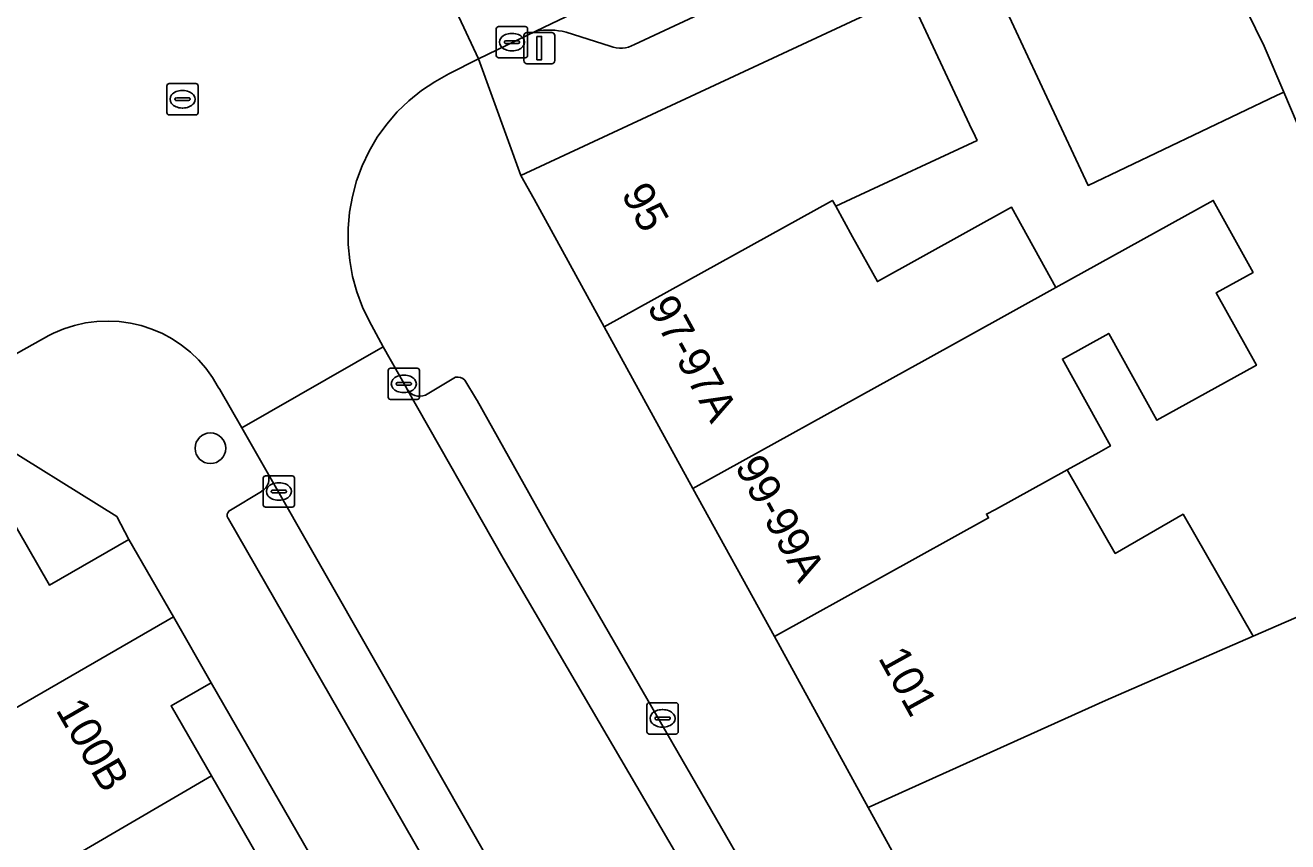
# Model space of a CAD drawing. Extents: x 160377 to 161131, y 383938 to 384853.
# Drawn here: x 160843.65 to 160884.05, y 384229.46 to 384255.57 of the extents above; entities that cross this region are included whole.
import ezdxf

# ---------------------------------------------------------------- set-up
doc = ezdxf.new("R2010")
doc.units = 0
for name, color, linetype in [('IMGEO_Boom', 7, 'Continuous'), ('IMGEO_Erf', 7, 'Continuous'), ('IMGEO_Kolk', 7, 'Continuous'), ('IMGEO_Lichtmast', 7, 'Continuous'), ('IMGEO_Pand', 7, 'Continuous'), ('IMGEO_Pand_nummerreeks', 7, 'Continuous'), ('IMGEO_Parkeervlak_open', 7, 'Continuous'), ('IMGEO_Rijbaan_lokaal_open', 7, 'Continuous'), ('IMGEO_Rioolput', 7, 'Continuous'), ('IMGEO_Voetpad_open', 7, 'Continuous')]:
    doc.layers.add(name, color=color, linetype=linetype)

msp = doc.modelspace()

# ---------------------------------------------------------------- linework, layer by layer
at = {"layer": 'IMGEO_Boom'}
msp.add_circle((160849.579, 384242.039), 0.489, dxfattribs=at)
at = {"layer": 'IMGEO_Erf'}
for points in [[(160886.167, 384256.23), (160888.975, 384249.661), (160886.06, 384248.416), (160883.919, 384253.426), (160883.691, 384253.317), (160877.662, 384250.445), (160876.42, 384253.107), (160874.307, 384257.638)], [(160871.93, 384256.552), (160873.871, 384252.392), (160874.044, 384252.021), (160874.109, 384251.882), (160870.067, 384250), (160869.586, 384249.776), (160870.128, 384248.798), (160870.919, 384247.37), (160875.213, 384249.746), (160876.634, 384247.177), (160881.668, 384249.963), (160882.94, 384247.663), (160881.764, 384247.013), (160883.046, 384244.696), (160879.861, 384242.933), (160878.324, 384245.711), (160876.839, 384244.889), (160878.375, 384242.112), (160878.005, 384241.907), (160876.993, 384241.347), (160878.528, 384238.679), (160880.703, 384239.931), (160882.946, 384236.033), (160891.632, 384239.808)], [(160842.395, 384241.187), (160844.426, 384237.664), (160846.964, 384239.127), (160846.586, 384239.857), (160842.364, 384242.484)]]:
    msp.add_lwpolyline(points, dxfattribs=at)
msp.add_lwpolyline([(160849.607, 384234.542), (160848.323, 384233.803), (160849.611, 384231.569), (160852.135, 384227.19), (160854.659, 384222.812), (160857.183, 384218.433), (160859.933, 384213.661), (160861.318, 384211.259), (160862.594, 384211.994)], close=True, dxfattribs=at)
at = {"layer": 'IMGEO_Kolk'}
for p, q in [((160858.801, 384255.527), (160859.653, 384255.527)), ((160858.726, 384254.601), (160858.726, 384255.453)), ((160859.028, 384255.07), (160859.426, 384255.07)), ((160859.214, 384255.307), (160859.239, 384255.307)), ((160859.727, 384255.453), (160859.727, 384254.601)), ((160858.985, 384255.021), (160858.985, 384255.033)), ((160859.423, 384254.984), (160859.025, 384254.984)), ((160859.237, 384254.747), (160859.212, 384254.747)), ((160859.469, 384255.033), (160859.469, 384255.021)), ((160859.653, 384254.527), (160858.801, 384254.527)), ((160855.342, 384244.599), (160856.194, 384244.599)), ((160855.267, 384243.673), (160855.267, 384244.525)), ((160855.755, 384244.379), (160855.78, 384244.379)), ((160856.268, 384244.525), (160856.268, 384243.673)), ((160855.526, 384244.093), (160855.526, 384244.105)), ((160855.964, 384244.056), (160855.566, 384244.056)), ((160855.569, 384244.142), (160855.967, 384244.142)), ((160855.778, 384243.819), (160855.753, 384243.819)), ((160856.01, 384244.105), (160856.01, 384244.093)), ((160856.194, 384243.599), (160855.342, 384243.599)), ((160851.269, 384240.232), (160851.269, 384241.084)), ((160851.344, 384241.158), (160852.196, 384241.158)), ((160851.757, 384240.938), (160851.782, 384240.938)), ((160852.27, 384241.084), (160852.27, 384240.232)), ((160851.528, 384240.652), (160851.528, 384240.664)), ((160851.966, 384240.615), (160851.568, 384240.615)), ((160851.571, 384240.701), (160851.969, 384240.701)), ((160852.012, 384240.664), (160852.012, 384240.652)), ((160852.196, 384240.158), (160851.344, 384240.158)), ((160851.78, 384240.378), (160851.755, 384240.378)), ((160863.546, 384232.976), (160863.546, 384233.828)), ((160863.621, 384233.902), (160864.473, 384233.902)), ((160864.034, 384233.682), (160864.059, 384233.682)), ((160864.547, 384233.828), (160864.547, 384232.976)), ((160863.805, 384233.396), (160863.805, 384233.408)), ((160864.243, 384233.359), (160863.845, 384233.359)), ((160863.848, 384233.445), (160864.246, 384233.445)), ((160864.289, 384233.408), (160864.289, 384233.396)), ((160864.473, 384232.902), (160863.621, 384232.902)), ((160864.057, 384233.122), (160864.032, 384233.122))]:
    msp.add_line(p, q, dxfattribs=at)
for points in [[(160858.801, 384255.527), (160859.653, 384255.527)], [(160858.726, 384254.601), (160858.726, 384255.453)], [(160859.727, 384255.453), (160859.727, 384254.601)], [(160859.653, 384254.527), (160858.801, 384254.527)], [(160855.342, 384244.599), (160856.194, 384244.599)], [(160855.267, 384243.673), (160855.267, 384244.525)], [(160856.268, 384244.525), (160856.268, 384243.673)], [(160856.194, 384243.599), (160855.342, 384243.599)], [(160851.269, 384240.232), (160851.269, 384241.084)], [(160851.344, 384241.158), (160852.196, 384241.158)], [(160852.27, 384241.084), (160852.27, 384240.232)], [(160852.196, 384240.158), (160851.344, 384240.158)], [(160863.546, 384232.976), (160863.546, 384233.828)], [(160863.621, 384233.902), (160864.473, 384233.902)], [(160864.547, 384233.828), (160864.547, 384232.976)], [(160864.473, 384232.902), (160863.621, 384232.902)]]:
    msp.add_lwpolyline(points, dxfattribs=at)
for centre, radius, start, end in [((160858.803, 384255.451), 0.0765, 91.552, 178.448), ((160858.803, 384255.451), 0.0765, 91.552, 178.448), ((160859.651, 384255.451), 0.0765, 1.552, 88.448), ((160859.651, 384255.451), 0.0765, 1.552, 88.448), ((160859.025, 384255.03), 0.0403, 85.8775, 175.7526), ((160859.43, 384255.032), 0.0386, 1.7309, 96.639), ((160859.022, 384255.02), 0.0366, 178.938, 274.7102), ((160859.426, 384255.027), 0.043, 264.8664, 352.4533), ((160858.803, 384254.603), 0.0765, 181.552, 268.448), ((160858.803, 384254.603), 0.0765, 181.552, 268.448), ((160859.651, 384254.603), 0.0765, 271.552, 358.448), ((160859.651, 384254.603), 0.0765, 271.552, 358.448), ((160855.344, 384244.523), 0.0765, 91.552, 178.448), ((160855.344, 384244.523), 0.0765, 91.552, 178.448), ((160856.192, 384244.523), 0.0765, 1.552, 88.448), ((160856.192, 384244.523), 0.0765, 1.552, 88.448), ((160855.566, 384244.102), 0.0403, 85.8775, 175.7526), ((160855.563, 384244.092), 0.0366, 178.938, 274.7102), ((160855.967, 384244.099), 0.043, 264.8664, 352.4533), ((160855.971, 384244.104), 0.0386, 1.7309, 96.639), ((160855.344, 384243.675), 0.0765, 181.552, 268.448), ((160855.344, 384243.675), 0.0765, 181.552, 268.448), ((160856.192, 384243.675), 0.0765, 271.552, 358.448), ((160856.192, 384243.675), 0.0765, 271.552, 358.448), ((160851.346, 384241.082), 0.0765, 91.552, 178.448), ((160851.346, 384241.082), 0.0765, 91.552, 178.448), ((160852.194, 384241.082), 0.0765, 1.552, 88.448), ((160852.194, 384241.082), 0.0765, 1.552, 88.448), ((160851.568, 384240.661), 0.0403, 85.8775, 175.7526), ((160851.565, 384240.651), 0.0366, 178.938, 274.7102), ((160851.969, 384240.658), 0.043, 264.8664, 352.4533), ((160851.973, 384240.663), 0.0386, 1.7309, 96.639), ((160851.346, 384240.234), 0.0765, 181.552, 268.448), ((160851.346, 384240.234), 0.0765, 181.552, 268.448), ((160852.194, 384240.234), 0.0765, 271.552, 358.448), ((160852.194, 384240.234), 0.0765, 271.552, 358.448), ((160863.623, 384233.826), 0.0765, 91.552, 178.448), ((160863.623, 384233.826), 0.0765, 91.552, 178.448), ((160864.471, 384233.826), 0.0765, 1.552, 88.448), ((160864.471, 384233.826), 0.0765, 1.552, 88.448), ((160863.845, 384233.405), 0.0403, 85.8775, 175.7526), ((160863.842, 384233.395), 0.0366, 178.938, 274.7102), ((160864.246, 384233.402), 0.043, 264.8664, 352.4533), ((160864.25, 384233.407), 0.0386, 1.7309, 96.639), ((160863.623, 384232.978), 0.0765, 181.552, 268.448), ((160863.623, 384232.978), 0.0765, 181.552, 268.448), ((160864.471, 384232.978), 0.0765, 271.552, 358.448), ((160864.471, 384232.978), 0.0765, 271.552, 358.448)]:
    msp.add_arc(centre, radius, start, end, dxfattribs=at)
for centre, major_axis, ratio, start_param, end_param in [((160859.213, 384255.027), (-0.387, 0.002), 0.722429, 4.712389, 7.853982), ((160859.238, 384255.027), (-0.39, 0.002), 0.717154, 1.570796, 4.712389), ((160855.754, 384244.099), (-0.387, 0.002), 0.722429, 4.712389, 7.853982), ((160855.779, 384244.099), (-0.39, 0.002), 0.717154, 1.570796, 4.712389), ((160851.756, 384240.658), (-0.387, 0.002), 0.722429, 4.712389, 7.853982), ((160851.781, 384240.658), (-0.39, 0.002), 0.717154, 1.570796, 4.712389), ((160864.033, 384233.402), (-0.387, 0.002), 0.722429, 4.712389, 7.853982), ((160864.058, 384233.402), (-0.39, 0.002), 0.717154, 1.570796, 4.712389)]:
    msp.add_ellipse(centre, major_axis=major_axis, ratio=ratio, start_param=start_param, end_param=end_param, dxfattribs=at)
at = {"layer": 'IMGEO_Lichtmast'}
for p, q in [((160859.608, 384254.436), (160859.608, 384255.236)), ((160859.608, 384255.236), (160859.608, 384254.436)), ((160859.708, 384255.336), (160860.498, 384255.336)), ((160860.498, 384255.336), (160859.708, 384255.336)), ((160860.598, 384255.236), (160860.598, 384254.436)), ((160860.598, 384254.436), (160860.598, 384255.236)), ((160860.498, 384254.336), (160859.708, 384254.336)), ((160859.708, 384254.336), (160860.498, 384254.336))]:
    msp.add_line(p, q, dxfattribs=at)
msp.add_lwpolyline([(160860.028, 384255.211), (160860.178, 384255.211), (160860.178, 384254.461), (160860.028, 384254.461), (160860.028, 384255.211)], dxfattribs=at)
for centre, start, end in [((160859.708, 384255.236), 90, 180), ((160859.708, 384255.236), 90, 180), ((160860.498, 384255.236), 0, 90), ((160860.498, 384255.236), 360, 90), ((160859.708, 384254.436), 180, 270), ((160859.708, 384254.436), 180, 270), ((160860.498, 384254.436), 270, 0), ((160860.498, 384254.436), 270, 0)]:
    msp.add_arc(centre, 0.1, start, end, dxfattribs=at)
at = {"layer": 'IMGEO_Pand'}
for points in [[(160885.248, 384264.503), (160879.686, 384261.908), (160880.361, 384260.462), (160880.531, 384260.54), (160883.292, 384254.893), (160883.919, 384253.426), (160886.06, 384248.416), (160888.975, 384249.661), (160886.167, 384256.23), (160888.58, 384257.352)], [(160880.361, 384260.462), (160874.307, 384257.638), (160876.42, 384253.107), (160877.662, 384250.445), (160883.691, 384253.317), (160883.919, 384253.426), (160883.292, 384254.893), (160880.531, 384260.54)], [(160874.109, 384251.882), (160874.044, 384252.021), (160873.871, 384252.392), (160871.93, 384256.552), (160859.514, 384250.759), (160859.934, 384250), (160862.177, 384245.922), (160869.482, 384249.964), (160869.586, 384249.776), (160870.067, 384250)], [(160876.634, 384247.177), (160875.213, 384249.746), (160870.919, 384247.37), (160870.128, 384248.798), (160869.586, 384249.776), (160869.482, 384249.964), (160862.177, 384245.922), (160865.02, 384240.752), (160871.915, 384244.567), (160872.342, 384244.803)], [(160876.839, 384244.889), (160878.324, 384245.711), (160879.861, 384242.933), (160883.046, 384244.696), (160881.764, 384247.013), (160882.94, 384247.663), (160881.668, 384249.963), (160876.634, 384247.177), (160872.342, 384244.803), (160871.915, 384244.567), (160865.02, 384240.752), (160867.623, 384236.02), (160874.477, 384239.812), (160874.409, 384239.935), (160874.703, 384240.08), (160876.993, 384241.347), (160878.005, 384241.907), (160878.375, 384242.112)], [(160882.946, 384236.033), (160880.703, 384239.931), (160878.528, 384238.679), (160876.993, 384241.347), (160874.703, 384240.08), (160874.409, 384239.935), (160874.477, 384239.812), (160867.623, 384236.02), (160870.628, 384230.556), (160878.215, 384233.977)], [(160848.395, 384236.644), (160846.964, 384239.127), (160844.426, 384237.664), (160842.395, 384241.187), (160832.974, 384235.756), (160834.16, 384233.699), (160836.437, 384229.749), (160839.083, 384231.275)], [(160899.008, 384223.96), (160891.632, 384239.808), (160882.946, 384236.033), (160878.215, 384233.977), (160870.628, 384230.556), (160872.611, 384226.95), (160874.008, 384227.747), (160885.41, 384208.137), (160884.021, 384207.323), (160885.643, 384204.556), (160903.567, 384214.961)], [(160849.611, 384231.569), (160848.323, 384233.803), (160849.607, 384234.542), (160848.395, 384236.644), (160839.083, 384231.275), (160841.607, 384226.897)], [(160852.135, 384227.19), (160849.611, 384231.569), (160841.607, 384226.897), (160844.131, 384222.518)]]:
    msp.add_lwpolyline(points, close=True, dxfattribs=at)
at = {"layer": 'IMGEO_Parkeervlak_open'}
for points in [[(160876.002, 384262.978), (160862.651, 384256.661), (160859.99, 384255.376)], [(160863.144, 384254.949), (160874.1, 384260.064)], [(160860.957, 384255.35), (160862.373, 384254.901)], [(160857.421, 384244.308), (160856.456, 384243.739)], [(160858.111, 384243.568), (160858.09, 384243.602), (160857.716, 384244.216)], [(160855.862, 384243.943), (160858.945, 384238.524), (160879.197, 384203.944)], [(160880.332, 384205.516), (160870.733, 384221.584), (160860.47, 384239.358), (160858.111, 384243.568)], [(160874.677, 384201.242), (160866.674, 384214.519), (160851.399, 384241.272)], [(160851.213, 384240.662), (160850.219, 384240.058)], [(160850.155, 384239.783), (160858.141, 384225.883), (160858.553, 384225.147)]]:
    msp.add_lwpolyline(points, dxfattribs=at)
for centre, radius, start, end in [((160860.409, 384252.952), 2.46, 77.1195, 99.8002), ((160862.711, 384255.687), 0.855, 246.7211, 300.4038), ((160857.487, 384244), 0.315, 43.2604, 102.098), ((160856.276, 384244.182), 0.478, 209.9766, 292.115), ((160851.006, 384241.059), 0.447, 297.5999, 28.4852), ((160850.29, 384239.897), 0.176, 113.7292, 220.0686)]:
    msp.add_arc(centre, radius, start, end, dxfattribs=at)
at = {"layer": 'IMGEO_Rijbaan_lokaal_open'}
for points in [[(160876.002, 384262.978), (160878.396, 384264.098), (160876.68, 384267.832), (160873.82, 384266.471), (160873.298, 384266.241), (160856.349, 384258.369), (160858.161, 384254.492), (160859.99, 384255.376), (160862.651, 384256.661)], [(160858.945, 384238.524), (160855.862, 384243.943), (160855.86, 384243.947), (160855.106, 384245.288), (160850.582, 384242.692), (160851.399, 384241.272), (160866.674, 384214.519), (160874.677, 384201.242), (160874.745, 384201.123), (160879.26, 384203.835), (160879.197, 384203.944)]]:
    msp.add_lwpolyline(points, close=True, dxfattribs=at)
msp.add_lwpolyline([(160841.926, 384244.257), (160844.411, 384245.642), (160844.563, 384245.718), (160844.894, 384245.858), (160845.236, 384245.967), (160845.587, 384246.046), (160845.944, 384246.093), (160846.303, 384246.108), (160846.662, 384246.091), (160847.018, 384246.042), (160847.369, 384245.962), (160847.71, 384245.85), (160848.041, 384245.708), (160848.357, 384245.537), (160848.657, 384245.339), (160848.938, 384245.115), (160849.198, 384244.866), (160849.435, 384244.596), (160849.646, 384244.305), (160849.831, 384243.996), (160849.878, 384243.916), (160850.582, 384242.692), (160855.106, 384245.288), (160854.733, 384245.98), (160854.672, 384246.091), (160854.448, 384246.555), (160854.266, 384247.038), (160854.128, 384247.535), (160854.035, 384248.042), (160853.987, 384248.556), (160853.986, 384249.072), (160854.031, 384249.585), (160854.121, 384250.093), (160854.256, 384250.591), (160854.436, 384251.074), (160854.658, 384251.54), (160854.92, 384251.984), (160855.221, 384252.403), (160855.559, 384252.793), (160855.93, 384253.151), (160856.331, 384253.475), (160856.76, 384253.762), (160857.212, 384254.009), (160858.161, 384254.492), (160856.349, 384258.369)], dxfattribs=at)
at = {"layer": 'IMGEO_Rioolput'}
for p, q in [((160848.187, 384252.774), (160848.187, 384253.626)), ((160848.262, 384253.7), (160849.114, 384253.7)), ((160848.675, 384253.48), (160848.7, 384253.48)), ((160849.188, 384253.626), (160849.188, 384252.774)), ((160848.446, 384253.194), (160848.446, 384253.206)), ((160848.884, 384253.157), (160848.486, 384253.157)), ((160848.489, 384253.243), (160848.887, 384253.243)), ((160848.93, 384253.206), (160848.93, 384253.194)), ((160849.114, 384252.7), (160848.262, 384252.7)), ((160848.698, 384252.92), (160848.673, 384252.92))]:
    msp.add_line(p, q, dxfattribs=at)
for points in [[(160848.187, 384252.774), (160848.187, 384253.626)], [(160848.262, 384253.7), (160849.114, 384253.7)], [(160849.188, 384253.626), (160849.188, 384252.774)], [(160849.114, 384252.7), (160848.262, 384252.7)]]:
    msp.add_lwpolyline(points, dxfattribs=at)
for centre, radius, start, end in [((160848.264, 384253.624), 0.0765, 91.552, 178.448), ((160848.264, 384253.624), 0.0765, 91.552, 178.448), ((160849.112, 384253.624), 0.0765, 1.552, 88.448), ((160849.112, 384253.624), 0.0765, 1.552, 88.448), ((160848.486, 384253.203), 0.0403, 85.8775, 175.7526), ((160848.483, 384253.193), 0.0366, 178.938, 274.7102), ((160848.887, 384253.2), 0.043, 264.8664, 352.4533), ((160848.891, 384253.205), 0.0386, 1.7309, 96.639), ((160848.264, 384252.776), 0.0765, 181.552, 268.448), ((160848.264, 384252.776), 0.0765, 181.552, 268.448), ((160849.112, 384252.776), 0.0765, 271.552, 358.448), ((160849.112, 384252.776), 0.0765, 271.552, 358.448)]:
    msp.add_arc(centre, radius, start, end, dxfattribs=at)
for centre, major_axis, ratio, start_param, end_param in [((160848.674, 384253.2), (-0.387, 0.002), 0.722429, 4.712389, 7.853982), ((160848.699, 384253.2), (-0.39, 0.002), 0.717154, 1.570796, 4.712389)]:
    msp.add_ellipse(centre, major_axis=major_axis, ratio=ratio, start_param=start_param, end_param=end_param, dxfattribs=at)
at = {"layer": 'IMGEO_Voetpad_open'}
for points in [[(160859.99, 384255.376), (160858.161, 384254.492), (160859.514, 384250.759), (160871.93, 384256.552), (160874.307, 384257.638), (160880.361, 384260.462), (160879.686, 384261.908), (160885.248, 384264.503), (160890.808, 384267.097), (160891.546, 384265.572), (160892.455, 384265.985), (160897.106, 384268.155), (160901.623, 384270.262), (160906.139, 384272.369), (160910.656, 384274.477), (160915.172, 384276.584), (160919.689, 384278.691), (160924.206, 384280.799), (160928.725, 384282.907), (160929.631, 384283.33), (160934.146, 384285.437), (160938.663, 384287.544), (160943.181, 384289.652)], [(160874.1, 384260.064), (160863.144, 384254.949)], [(160862.373, 384254.901), (160860.957, 384255.35)], [(160867.623, 384236.02), (160865.02, 384240.752), (160862.177, 384245.922), (160859.934, 384250), (160859.514, 384250.759), (160858.161, 384254.492), (160857.212, 384254.009), (160856.76, 384253.762), (160856.331, 384253.475), (160855.93, 384253.151), (160855.559, 384252.793), (160855.221, 384252.403), (160854.92, 384251.984), (160854.658, 384251.54), (160854.436, 384251.074), (160854.256, 384250.591), (160854.121, 384250.093), (160854.031, 384249.585), (160853.986, 384249.072), (160853.987, 384248.556), (160854.035, 384248.042), (160854.128, 384247.535), (160854.266, 384247.038), (160854.448, 384246.555), (160854.672, 384246.091), (160854.733, 384245.98), (160855.106, 384245.288), (160855.86, 384243.947), (160855.862, 384243.943)], [(160851.399, 384241.272), (160850.582, 384242.692), (160849.878, 384243.916), (160849.831, 384243.996), (160849.646, 384244.305), (160849.435, 384244.596), (160849.198, 384244.866), (160848.938, 384245.115), (160848.657, 384245.339), (160848.357, 384245.537), (160848.041, 384245.708), (160847.71, 384245.85), (160847.369, 384245.962), (160847.018, 384246.042), (160846.662, 384246.091), (160846.303, 384246.108), (160845.944, 384246.093), (160845.587, 384246.046), (160845.236, 384245.967), (160844.894, 384245.858), (160844.563, 384245.718), (160844.411, 384245.642), (160841.926, 384244.257)], [(160856.456, 384243.739), (160857.421, 384244.308)], [(160857.716, 384244.216), (160858.09, 384243.602), (160858.111, 384243.568), (160860.47, 384239.358), (160870.733, 384221.584), (160880.332, 384205.516)], [(160842.364, 384242.484), (160846.586, 384239.857), (160846.964, 384239.127), (160848.395, 384236.644), (160849.607, 384234.542), (160862.594, 384211.994)], [(160850.219, 384240.058), (160851.213, 384240.662)], [(160858.553, 384225.147), (160858.141, 384225.883), (160850.155, 384239.783)], [(160872.611, 384226.95), (160870.628, 384230.556), (160867.623, 384236.02)]]:
    msp.add_lwpolyline(points, dxfattribs=at)
for centre, radius, start, end in [((160860.409, 384252.952), 2.46, 77.1195, 99.8002), ((160862.711, 384255.687), 0.855, 246.7211, 300.4038), ((160857.487, 384244), 0.315, 43.2604, 102.098), ((160856.276, 384244.182), 0.478, 209.9766, 292.115), ((160851.006, 384241.059), 0.447, 297.5999, 28.4852), ((160850.29, 384239.897), 0.176, 113.7292, 220.0686)]:
    msp.add_arc(centre, radius, start, end, dxfattribs=at)

# ---------------------------------------------------------------- texts
at = {"layer": 'IMGEO_Pand_nummerreeks'}
for s, rotation, p in [('95', 298.6821, (160862.707, 384250.175)), ('97-97A', 298.8081, (160863.532, 384246.571)), ('99-99A', 298.8138, (160866.341, 384241.463)), ('101', 298.9513, (160870.928, 384235.338)), ('100B', 299.9622, (160844.612, 384233.672))]:
    msp.add_text(s, height=1, rotation=rotation, dxfattribs=at).set_placement(p)

doc.saveas('drawing.dxf')
